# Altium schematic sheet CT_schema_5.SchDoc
size 373 x 245 mm
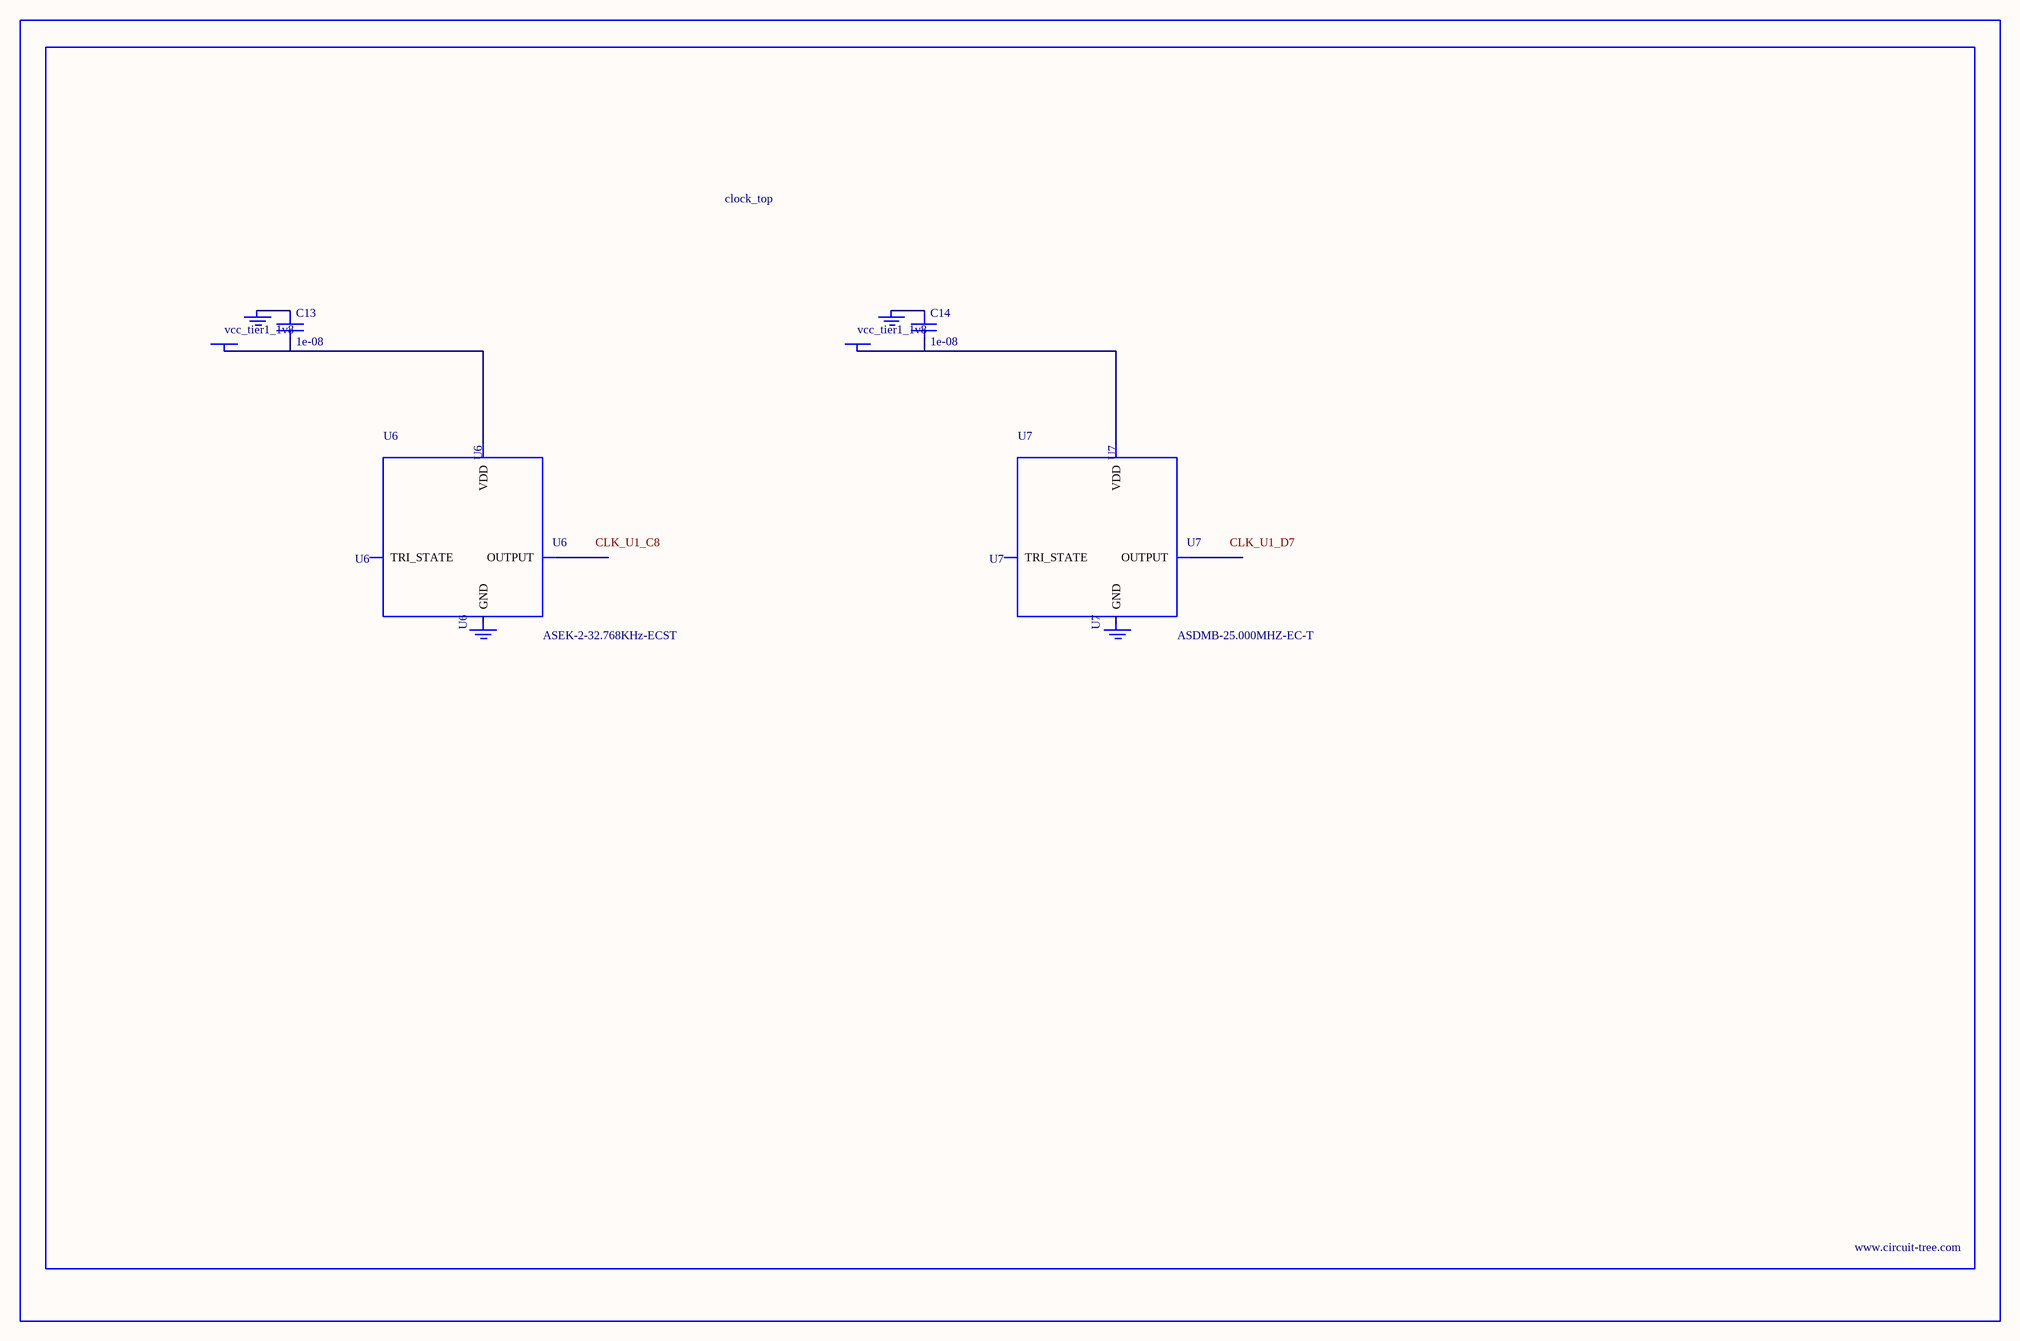
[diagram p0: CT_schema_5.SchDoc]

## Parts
BORDER4  (no value)
C13  1e-08  [C0402]
C14  1e-08  [C0402]
GND_INSTANCE_4_0  (no value)
GND_INSTANCE_4_1  (no value)
GND_INSTANCE_4_2  (no value)
GND_INSTANCE_4_3  (no value)
POWER_INSTANCE_4_0  vcc_tier1_1v8
POWER_INSTANCE_4_1  vcc_tier1_1v8
U6  ASEK-2-32.768KHz-ECST  [ASEK]
U7  ASDMB-25.000MHZ-EC-T  [ASDMB-XX.XXXXMHZ-XX-XX-XXX]

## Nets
NetC13_1: C13.1 GND_INSTANCE_4_0.0(GND)
NetC13_2: C13.2 POWER_INSTANCE_4_0.0(PWR) U6.4(VDD)
NetC14_1: C14.1 GND_INSTANCE_4_2.0(GND)
NetC14_2: C14.2 POWER_INSTANCE_4_1.0(PWR) U7.4(VDD)

Not connected (* = marked no-connect by the designer): GND_INSTANCE_4_1 0(GND); GND_INSTANCE_4_3 0(GND); U6 1(TRI_STATE) 2(GND) 3(OUTPUT); U7 1(TRI_STATE) 2(GND) 3(OUTPUT)

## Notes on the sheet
- Labels drawn without touching a wire or pin: CLK_U1_C8, CLK_U1_D7

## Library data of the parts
BORDER4 = BORDER_PAGE4
C13 C14 = C0402C103K3RAC
GND_INSTANCE_4_0-GND_INSTANCE_4_3 = GND
POWER_INSTANCE_4_0 POWER_INSTANCE_4_1 = PWR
